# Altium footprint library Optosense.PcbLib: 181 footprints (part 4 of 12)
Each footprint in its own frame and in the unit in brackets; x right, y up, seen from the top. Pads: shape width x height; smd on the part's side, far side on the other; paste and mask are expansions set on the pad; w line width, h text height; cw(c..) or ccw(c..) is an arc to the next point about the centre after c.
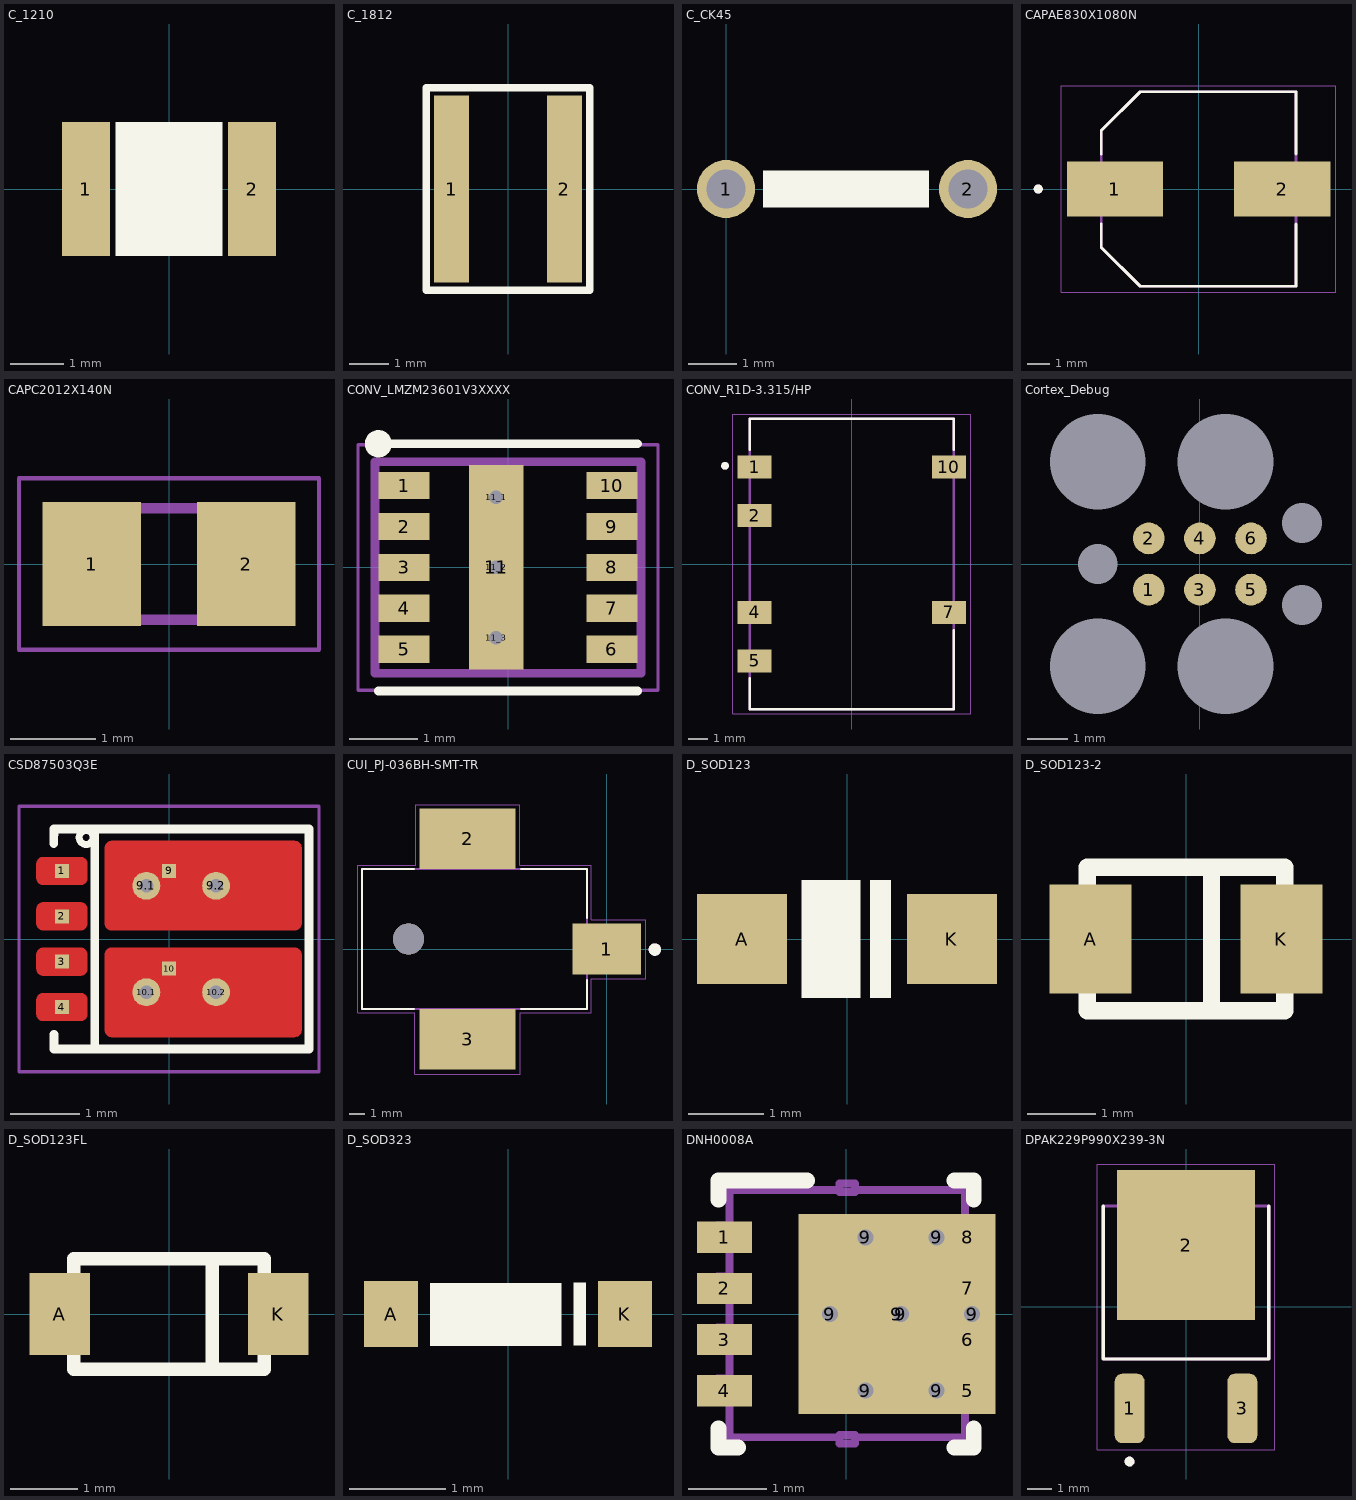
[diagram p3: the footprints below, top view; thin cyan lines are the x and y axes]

## C_1210 [mm]
pads (2):
  rect 0.9x2.5 smd: 1(-1.55,0) 2(1.55,0)
Top Overlay:
  rectangle: -1,-1.25 1,1.25
3D body "12105C335JAT2A.stp": height 2.79, standoff 0, extent -1.65,-1.25 1.65,1.25

## C_1812 [mm]
height 0.55
pads (2):
  rect 0.9x4.8 smd: 1(-1.45,0) 2(1.45,0)
Top Overlay:
  lines w0.2: -2.1,-2.6 -2.1,2.6 2.1,2.6 2.1,-2.6 -2.1,-2.6

## C_CK45 [mm]
pads (2):
  round 1.2 hole 0.8: 1(0,0) 2(5,0)
Top Overlay:
  rectangle: 0.762,-0.381 4.191,0.381
3D body "User Library-TDK_CAP_CK45_.STEP": height 12.5, standoff -5, extent -3.053,-2.503 7.939,2.497

## CAPAE830X1080N [mm]
pads (2):
  rect 4.21x2.42 smd: 1(-3.65,0) 2(3.65,0)
Top Overlay:
  circle w0.2: c-7,0 r0.1
  lines w0.127: -4.25,-1.53 -4.25,-2.55 -2.55,-4.25 4.25,-4.25 4.25,-1.53 ; -4.25,1.53 -4.25,2.55 -2.55,4.25 4.25,4.25 4.25,1.53
Mechanical 13:
  circle w0.2: c-7,0 r0.1
  lines w0.127: -4.25,-2.55 -4.25,2.55 -2.55,4.25 4.25,4.25 4.25,-4.25 -2.55,-4.25 -4.25,-2.55
Mechanical 15:
  lines w0.05: -6.005,-4.5 -6.005,4.5 6.005,4.5 6.005,-4.5 -6.005,-4.5
3D body "EEE-2AA100P.STEP": height 10.5, standoff 0, extent -5,-4.15 5,4.15

## CAPC2012X140N [mm]
pads (2):
  rect 1.15x1.45 smd: 1(-0.9,0) 2(0.9,0)
Mechanical 13:
  region: -0.5,-0.665 -1.023,-0.665 -1.023,0.65 -0.5,0.65
  region: 1,-0.668 0.514,-0.668 0.514,0.65 1,0.65
  lines w0.127: -1,-0.65 1,-0.65 1,0.65 -1,0.65 -1,-0.65
Mechanical 15:
  lines w0.05: -1.75,-1 1.75,-1 1.75,1 -1.75,1 -1.75,-1

## CONV_LMZM23601V3XXXX [mm]
pads (14):
  rect 0.75x0.4 smd paste-0.1 mask+0: 1(-1.525,1.2) 2(-1.525,0.6) 3(-1.525,0) 4(-1.525,-0.6) 5(-1.525,-1.2) 6(1.525,-1.2) 7(1.525,-0.6) 8(1.525,0) 9(1.525,0.6) 10(1.525,1.2)
  rect 0.8x3 smd paste-0.25 mask+0: 11(-0.175,0)
  round 0.4 hole 0.2 mask+0: 11_1(-0.175,1.03) 11_2(-0.175,0) 11_3(-0.175,-1.03)
Top Overlay:
  circle w0.2: c-1.9,1.813 r0.1
  lines w0.127: -1.9,-1.813 1.9,-1.813 ; -1.9,1.813 1.9,1.813
Top Paste:
  region: 1.85,-1.35 1.2,-1.35 1.2,-1.05 1.85,-1.05
  region: 1.85,-0.75 1.2,-0.75 1.2,-0.45 1.85,-0.45
  region: 1.85,-0.15 1.2,-0.15 1.2,0.15 1.85,0.15
  region: 1.85,0.45 1.2,0.45 1.2,0.75 1.85,0.75
  region: 1.85,1.05 1.2,1.05 1.2,1.35 1.85,1.35
  region: -1.2,-1.35 -1.85,-1.35 -1.85,-1.05 -1.2,-1.05
  region: -1.2,-0.75 -1.85,-0.75 -1.85,-0.45 -1.2,-0.45
  region: -1.2,-0.15 -1.85,-0.15 -1.85,0.15 -1.2,0.15
  region: -1.2,0.45 -1.85,0.45 -1.85,0.75 -1.2,0.75
  region: -1.2,1.05 -1.85,1.05 -1.85,1.35 -1.2,1.35
  region: 0.175,-1.446 -0.525,-1.446 -0.525,-0.613 0.175,-0.613
  region: 0.175,-0.416 -0.525,-0.416 -0.525,0.416 0.175,0.416
  region: 0.175,0.613 -0.525,0.613 -0.525,1.446 0.175,1.446
Top Solder:
  region: 1.85,-1.35 1.2,-1.35 1.2,-1.05 1.85,-1.05
  region: 1.85,-0.75 1.2,-0.75 1.2,-0.45 1.85,-0.45
  region: 1.85,1.05 1.2,1.05 1.2,1.35 1.85,1.35
  region: 1.85,0.45 1.2,0.45 1.2,0.75 1.85,0.75
  region: -1.2,-1.35 -1.85,-1.35 -1.85,-1.05 -1.2,-1.05
  region: -1.2,-0.75 -1.85,-0.75 -1.85,-0.45 -1.2,-0.45
  region: -1.2,1.05 -1.85,1.05 -1.85,1.35 -1.2,1.35
  region: -1.2,0.45 -1.85,0.45 -1.85,0.75 -1.2,0.75
  region: 1.85,-0.15 1.2,-0.15 1.2,0.15 1.85,0.15
  region: -1.2,-0.15 -1.85,-0.15 -1.85,0.15 -1.2,0.15
  region: 0.175,-1.45 -0.525,-1.45 -0.525,1.45 0.175,1.45
Mechanical 13:
  lines w0.127: -1.95,-1.55 1.95,-1.55 1.95,1.55 -1.95,1.55 -1.95,-1.55
Mechanical 15:
  lines w0.05: -2.2,-1.8 2.2,-1.8 2.2,1.8 -2.2,1.8 -2.2,-1.8
3D body "PLMZM23601SILR--3DModel-STEP-56544.STEP": height 1.58, standoff 0, extent -1.9,-1.5 1.9,1.5

## CONV_R1D-3.315/HP [mm]
pads (6):
  rect 1.8x1.2 smd: 1(-5.1,5.08) 2(-5.1,2.54) 4(-5.1,-2.54) 5(-5.1,-5.08) 7(5.1,-2.54) 10(5.1,5.08)
Top Overlay:
  circle w0.2: c-6.65,5.15 r0.1
  lines w0.127: -5.35,-6 -5.35,-7.62 5.35,-7.62 5.35,-3.47 ; -5.35,6 -5.35,7.62 5.35,7.62 5.35,6
Mechanical 13:
  circle w0.2: c-6.65,5.15 r0.1
  lines w0.127: -5.35,-7.62 -5.35,7.62 5.35,7.62 5.35,-7.62 -5.35,-7.62
Mechanical 15:
  lines w0.05: -6.25,-7.87 -6.25,7.87 6.25,7.87 6.25,-7.87 -6.25,-7.87
3D body "R1D-3.315-HP--3DModel-STEP-1.STEP": height 7.05, standoff 0.05, extent -5.423,-7.625 5.677,7.625

## Cortex_Debug [mm]
pads (13):
  round 0.787 smd paste+0 mask+0: 1(-1.27,-0.635) 2(-1.27,0.635) 3(0,-0.635) 4(0,0.635) 5(1.27,-0.635) 6(1.27,0.635)
  round 0.787 hole 2.375 paste+0 mask+0: ""(-2.54,-2.54) ""(-2.54,2.54) ""(0.635,-2.54) ""(0.635,2.54)
  round 0.787 hole 0.991 paste+0 mask+0: ""(-2.54,0) ""(2.54,-1.016) ""(2.54,1.016)

## CSD87503Q3E [mm]
pads (10):
  rect 0.2x0.2 smd paste-1 mask+0: 1(-1.535,0.975) 2(-1.535,0.325) 3(-1.535,-0.325) 4(-1.535,-0.975) 9(0,0.975) 10(0,-0.425)
  round 0.4 hole 0.2 mask+0: 9.1(-0.325,0.763) 9.2(0.675,0.763) 10.1(-0.325,-0.763) 10.2(0.675,-0.763)
Top Layer:
  region: 1.805,-0.125 1.81,-0.126 1.816,-0.126 1.821,-0.127 1.826,-0.128 1.831,-0.13 1.836,-0.132 1.841,-0.134 1.845,-0.136 1.85,-0.138 1.854,-0.141 1.859,-0.144 1.863,-0.147 1.867,-0.151 1.871,-0.154 1.874,-0.158 1.878,-0.162 1.881,-0.166 1.884,-0.171 1.887,-0.175 1.889,-0.18 1.891,-0.184 1.893,-0.189 1.895,-0.194 1.897,-0.199 1.898,-0.204 1.899,-0.209 1.899,-0.215 1.9,-0.22 1.9,-0.225 1.9,-1.305 1.9,-1.31 1.899,-1.315 1.899,-1.321 1.898,-1.326 1.897,-1.331 1.895,-1.336 1.893,-1.341 1.891,-1.346 1.889,-1.35 1.887,-1.355 1.884,-1.359 1.881,-1.364 1.878,-1.368 1.874,-1.372 1.871,-1.376 1.867,-1.379 1.863,-1.383 1.859,-1.386 1.854,-1.389 1.85,-1.392 1.845,-1.394 1.841,-1.396 1.836,-1.398 1.831,-1.4 1.826,-1.402 1.821,-1.403 1.816,-1.404 1.81,-1.404 1.805,-1.405 1.8,-1.405 -0.82,-1.405 -0.825,-1.405 -0.83,-1.404 -0.836,-1.404 -0.841,-1.403 -0.846,-1.402 -0.851,-1.4 -0.856,-1.398 -0.861,-1.396 -0.865,-1.394 -0.87,-1.392 -0.874,-1.389 -0.879,-1.386 -0.883,-1.383 -0.887,-1.379 -0.891,-1.376 -0.894,-1.372 -0.898,-1.368 -0.901,-1.364 -0.904,-1.359 -0.907,-1.355 -0.909,-1.35 -0.911,-1.346 -0.913,-1.341 -0.915,-1.336 -0.917,-1.331 -0.918,-1.326 -0.919,-1.321 -0.919,-1.315 -0.92,-1.31 -0.92,-1.305 -0.92,-0.225 -0.92,-0.22 -0.919,-0.215 -0.919,-0.209 -0.918,-0.204 -0.917,-0.199 -0.915,-0.194 -0.913,-0.189 -0.911,-0.184 -0.909,-0.18 -0.907,-0.175 -0.904,-0.171 -0.901,-0.166 -0.898,-0.162 -0.894,-0.158 -0.891,-0.154 -0.887,-0.151 -0.883,-0.147 -0.879,-0.144 -0.874,-0.141 -0.87,-0.138 -0.865,-0.136 -0.861,-0.134 -0.856,-0.132 -0.851,-0.13 -0.846,-0.128 -0.841,-0.127 -0.836,-0.126 -0.83,-0.126 -0.825,-0.125 -0.82,-0.125 1.8,-0.125
  region: 1.805,1.405 1.81,1.404 1.816,1.404 1.821,1.403 1.826,1.402 1.831,1.4 1.836,1.398 1.841,1.396 1.845,1.394 1.85,1.392 1.854,1.389 1.859,1.386 1.863,1.383 1.867,1.379 1.871,1.376 1.874,1.372 1.878,1.368 1.881,1.364 1.884,1.359 1.887,1.355 1.889,1.35 1.891,1.346 1.893,1.341 1.895,1.336 1.897,1.331 1.898,1.326 1.899,1.321 1.899,1.315 1.9,1.31 1.9,1.305 1.9,0.225 1.9,0.22 1.899,0.215 1.899,0.209 1.898,0.204 1.897,0.199 1.895,0.194 1.893,0.189 1.891,0.184 1.889,0.18 1.887,0.175 1.884,0.171 1.881,0.166 1.878,0.162 1.874,0.158 1.871,0.154 1.867,0.151 1.863,0.147 1.859,0.144 1.854,0.141 1.85,0.138 1.845,0.136 1.841,0.134 1.836,0.132 1.831,0.13 1.826,0.128 1.821,0.127 1.816,0.126 1.81,0.126 1.805,0.125 1.8,0.125 -0.82,0.125 -0.825,0.125 -0.83,0.126 -0.836,0.126 -0.841,0.127 -0.846,0.128 -0.851,0.13 -0.856,0.132 -0.861,0.134 -0.865,0.136 -0.87,0.138 -0.874,0.141 -0.879,0.144 -0.883,0.147 -0.887,0.151 -0.891,0.154 -0.894,0.158 -0.898,0.162 -0.901,0.166 -0.904,0.171 -0.907,0.175 -0.909,0.18 -0.911,0.184 -0.913,0.189 -0.915,0.194 -0.917,0.199 -0.918,0.204 -0.919,0.209 -0.919,0.215 -0.92,0.22 -0.92,0.225 -0.92,1.305 -0.92,1.31 -0.919,1.315 -0.919,1.321 -0.918,1.326 -0.917,1.331 -0.915,1.336 -0.913,1.341 -0.911,1.346 -0.909,1.35 -0.907,1.355 -0.904,1.359 -0.901,1.364 -0.898,1.368 -0.894,1.372 -0.891,1.376 -0.887,1.379 -0.883,1.383 -0.879,1.386 -0.874,1.389 -0.87,1.392 -0.865,1.394 -0.861,1.396 -0.856,1.398 -0.851,1.4 -0.846,1.402 -0.841,1.403 -0.836,1.404 -0.83,1.404 -0.825,1.405 -0.82,1.405 1.8,1.405
  region: -1.265,-0.775 -1.26,-0.776 -1.254,-0.776 -1.249,-0.777 -1.244,-0.778 -1.239,-0.78 -1.234,-0.782 -1.229,-0.784 -1.225,-0.786 -1.22,-0.788 -1.216,-0.791 -1.211,-0.794 -1.207,-0.797 -1.203,-0.801 -1.199,-0.804 -1.196,-0.808 -1.192,-0.812 -1.189,-0.816 -1.186,-0.821 -1.183,-0.825 -1.181,-0.83 -1.179,-0.834 -1.177,-0.839 -1.175,-0.844 -1.173,-0.849 -1.172,-0.854 -1.171,-0.859 -1.171,-0.865 -1.17,-0.87 -1.17,-0.875 -1.17,-1.075 -1.17,-1.08 -1.171,-1.085 -1.171,-1.091 -1.172,-1.096 -1.173,-1.101 -1.175,-1.106 -1.177,-1.111 -1.179,-1.116 -1.181,-1.12 -1.183,-1.125 -1.186,-1.129 -1.189,-1.134 -1.192,-1.138 -1.196,-1.142 -1.199,-1.146 -1.203,-1.149 -1.207,-1.153 -1.211,-1.156 -1.216,-1.159 -1.22,-1.162 -1.225,-1.164 -1.229,-1.166 -1.234,-1.168 -1.239,-1.17 -1.244,-1.172 -1.249,-1.173 -1.254,-1.174 -1.26,-1.174 -1.265,-1.175 -1.27,-1.175 -1.8,-1.175 -1.805,-1.175 -1.81,-1.174 -1.816,-1.174 -1.821,-1.173 -1.826,-1.172 -1.831,-1.17 -1.836,-1.168 -1.841,-1.166 -1.845,-1.164 -1.85,-1.162 -1.854,-1.159 -1.859,-1.156 -1.863,-1.153 -1.867,-1.149 -1.871,-1.146 -1.874,-1.142 -1.878,-1.138 -1.881,-1.134 -1.884,-1.129 -1.887,-1.125 -1.889,-1.12 -1.891,-1.116 -1.893,-1.111 -1.895,-1.106 -1.897,-1.101 -1.898,-1.096 -1.899,-1.091 -1.899,-1.085 -1.9,-1.08 -1.9,-1.075 -1.9,-0.875 -1.9,-0.87 -1.899,-0.865 -1.899,-0.859 -1.898,-0.854 -1.897,-0.849 -1.895,-0.844 -1.893,-0.839 -1.891,-0.834 -1.889,-0.83 -1.887,-0.825 -1.884,-0.821 -1.881,-0.816 -1.878,-0.812 -1.874,-0.808 -1.871,-0.804 -1.867,-0.801 -1.863,-0.797 -1.859,-0.794 -1.854,-0.791 -1.85,-0.788 -1.845,-0.786 -1.841,-0.784 -1.836,-0.782 -1.831,-0.78 -1.826,-0.778 -1.821,-0.777 -1.816,-0.776 -1.81,-0.776 -1.805,-0.775 -1.8,-0.775 -1.27,-0.775
  region: -1.265,1.175 -1.26,1.174 -1.254,1.174 -1.249,1.173 -1.244,1.172 -1.239,1.17 -1.234,1.168 -1.229,1.166 -1.225,1.164 -1.22,1.162 -1.216,1.159 -1.211,1.156 -1.207,1.153 -1.203,1.149 -1.199,1.146 -1.196,1.142 -1.192,1.138 -1.189,1.134 -1.186,1.129 -1.183,1.125 -1.181,1.12 -1.179,1.116 -1.177,1.111 -1.175,1.106 -1.173,1.101 -1.172,1.096 -1.171,1.091 -1.171,1.085 -1.17,1.08 -1.17,1.075 -1.17,0.875 -1.17,0.87 -1.171,0.865 -1.171,0.859 -1.172,0.854 -1.173,0.849 -1.175,0.844 -1.177,0.839 -1.179,0.834 -1.181,0.83 -1.183,0.825 -1.186,0.821 -1.189,0.816 -1.192,0.812 -1.196,0.808 -1.199,0.804 -1.203,0.801 -1.207,0.797 -1.211,0.794 -1.216,0.791 -1.22,0.788 -1.225,0.786 -1.229,0.784 -1.234,0.782 -1.239,0.78 -1.244,0.778 -1.249,0.777 -1.254,0.776 -1.26,0.776 -1.265,0.775 -1.27,0.775 -1.8,0.775 -1.805,0.775 -1.81,0.776 -1.816,0.776 -1.821,0.777 -1.826,0.778 -1.831,0.78 -1.836,0.782 -1.841,0.784 -1.845,0.786 -1.85,0.788 -1.854,0.791 -1.859,0.794 -1.863,0.797 -1.867,0.801 -1.871,0.804 -1.874,0.808 -1.878,0.812 -1.881,0.816 -1.884,0.821 -1.887,0.825 -1.889,0.83 -1.891,0.834 -1.893,0.839 -1.895,0.844 -1.897,0.849 -1.898,0.854 -1.899,0.859 -1.899,0.865 -1.9,0.87 -1.9,0.875 -1.9,1.075 -1.9,1.08 -1.899,1.085 -1.899,1.091 -1.898,1.096 -1.897,1.101 -1.895,1.106 -1.893,1.111 -1.891,1.116 -1.889,1.12 -1.887,1.125 -1.884,1.129 -1.881,1.134 -1.878,1.138 -1.874,1.142 -1.871,1.146 -1.867,1.149 -1.863,1.153 -1.859,1.156 -1.854,1.159 -1.85,1.162 -1.845,1.164 -1.841,1.166 -1.836,1.168 -1.831,1.17 -1.826,1.172 -1.821,1.173 -1.816,1.174 -1.81,1.174 -1.805,1.175 -1.8,1.175 -1.27,1.175
  region: -1.265,0.525 -1.26,0.524 -1.254,0.524 -1.249,0.523 -1.244,0.522 -1.239,0.52 -1.234,0.518 -1.229,0.516 -1.225,0.514 -1.22,0.512 -1.216,0.509 -1.211,0.506 -1.207,0.503 -1.203,0.499 -1.199,0.496 -1.196,0.492 -1.192,0.488 -1.189,0.484 -1.186,0.479 -1.183,0.475 -1.181,0.47 -1.179,0.466 -1.177,0.461 -1.175,0.456 -1.173,0.451 -1.172,0.446 -1.171,0.441 -1.171,0.435 -1.17,0.43 -1.17,0.425 -1.17,0.225 -1.17,0.22 -1.171,0.215 -1.171,0.209 -1.172,0.204 -1.173,0.199 -1.175,0.194 -1.177,0.189 -1.179,0.184 -1.181,0.18 -1.183,0.175 -1.186,0.171 -1.189,0.166 -1.192,0.162 -1.196,0.158 -1.199,0.154 -1.203,0.151 -1.207,0.147 -1.211,0.144 -1.216,0.141 -1.22,0.138 -1.225,0.136 -1.229,0.134 -1.234,0.132 -1.239,0.13 -1.244,0.128 -1.249,0.127 -1.254,0.126 -1.26,0.126 -1.265,0.125 -1.27,0.125 -1.8,0.125 -1.805,0.125 -1.81,0.126 -1.816,0.126 -1.821,0.127 -1.826,0.128 -1.831,0.13 -1.836,0.132 -1.841,0.134 -1.845,0.136 -1.85,0.138 -1.854,0.141 -1.859,0.144 -1.863,0.147 -1.867,0.151 -1.871,0.154 -1.874,0.158 -1.878,0.162 -1.881,0.166 -1.884,0.171 -1.887,0.175 -1.889,0.18 -1.891,0.184 -1.893,0.189 -1.895,0.194 -1.897,0.199 -1.898,0.204 -1.899,0.209 -1.899,0.215 -1.9,0.22 -1.9,0.225 -1.9,0.425 -1.9,0.43 -1.899,0.435 -1.899,0.441 -1.898,0.446 -1.897,0.451 -1.895,0.456 -1.893,0.461 -1.891,0.466 -1.889,0.47 -1.887,0.475 -1.884,0.479 -1.881,0.484 -1.878,0.488 -1.874,0.492 -1.871,0.496 -1.867,0.499 -1.863,0.503 -1.859,0.506 -1.854,0.509 -1.85,0.512 -1.845,0.514 -1.841,0.516 -1.836,0.518 -1.831,0.52 -1.826,0.522 -1.821,0.523 -1.816,0.524 -1.81,0.524 -1.805,0.525 -1.8,0.525 -1.27,0.525
  region: -1.265,-0.125 -1.26,-0.126 -1.254,-0.126 -1.249,-0.127 -1.244,-0.128 -1.239,-0.13 -1.234,-0.132 -1.229,-0.134 -1.225,-0.136 -1.22,-0.138 -1.216,-0.141 -1.211,-0.144 -1.207,-0.147 -1.203,-0.151 -1.199,-0.154 -1.196,-0.158 -1.192,-0.162 -1.189,-0.166 -1.186,-0.171 -1.183,-0.175 -1.181,-0.18 -1.179,-0.184 -1.177,-0.189 -1.175,-0.194 -1.173,-0.199 -1.172,-0.204 -1.171,-0.209 -1.171,-0.215 -1.17,-0.22 -1.17,-0.225 -1.17,-0.425 -1.17,-0.43 -1.171,-0.435 -1.171,-0.441 -1.172,-0.446 -1.173,-0.451 -1.175,-0.456 -1.177,-0.461 -1.179,-0.466 -1.181,-0.47 -1.183,-0.475 -1.186,-0.479 -1.189,-0.484 -1.192,-0.488 -1.196,-0.492 -1.199,-0.496 -1.203,-0.499 -1.207,-0.503 -1.211,-0.506 -1.216,-0.509 -1.22,-0.512 -1.225,-0.514 -1.229,-0.516 -1.234,-0.518 -1.239,-0.52 -1.244,-0.522 -1.249,-0.523 -1.254,-0.524 -1.26,-0.524 -1.265,-0.525 -1.27,-0.525 -1.8,-0.525 -1.805,-0.525 -1.81,-0.524 -1.816,-0.524 -1.821,-0.523 -1.826,-0.522 -1.831,-0.52 -1.836,-0.518 -1.841,-0.516 -1.845,-0.514 -1.85,-0.512 -1.854,-0.509 -1.859,-0.506 -1.863,-0.503 -1.867,-0.499 -1.871,-0.496 -1.874,-0.492 -1.878,-0.488 -1.881,-0.484 -1.884,-0.479 -1.887,-0.475 -1.889,-0.47 -1.891,-0.466 -1.893,-0.461 -1.895,-0.456 -1.897,-0.451 -1.898,-0.446 -1.899,-0.441 -1.899,-0.435 -1.9,-0.43 -1.9,-0.425 -1.9,-0.225 -1.9,-0.22 -1.899,-0.215 -1.899,-0.209 -1.898,-0.204 -1.897,-0.199 -1.895,-0.194 -1.893,-0.189 -1.891,-0.184 -1.889,-0.18 -1.887,-0.175 -1.884,-0.171 -1.881,-0.166 -1.878,-0.162 -1.874,-0.158 -1.871,-0.154 -1.867,-0.151 -1.863,-0.147 -1.859,-0.144 -1.854,-0.141 -1.85,-0.138 -1.845,-0.136 -1.841,-0.134 -1.836,-0.132 -1.831,-0.13 -1.826,-0.128 -1.821,-0.127 -1.816,-0.126 -1.81,-0.126 -1.805,-0.125 -1.8,-0.125 -1.27,-0.125
Top Overlay:
  circle w0.1: c-1.188,1.455 r0.1
  rectangle: -1.125,-1.575 -1,1.611
  lines w0.127: -1.652,1.371 -1.651,1.575 2.007,1.575 2.007,-1.575 -1.649,-1.575 -1.648,-1.371
Top Paste:
  drawing of 10 lines, arcs and shapes, not listed
Top Solder:
  drawing of 6 lines, arcs and shapes, not listed
Mechanical 15:
  lines w0.05: -2.15,-1.9 -2.15,1.9 2.15,1.9 2.15,-1.9 -2.15,-1.9
3D body "CSD17551Q3A.STEP": height 0.9, standoff 0, extent -1.599,-1.75 1.701,1.7

## CUI_PJ-036BH-SMT-TR [mm]
pads (4):
  rect 4.4x3.3 smd: 1(0,0)
  rect 6.2x3.9 smd: 2(-8.95,7.1) 3(-8.95,-5.8)
  round 2 hole 2 unplated: ""(-12.75,0.65)
Top Overlay:
  circle w0.4: c3.104,-0.03 r0.2
  lines w0.127: -12.4,-3.85 -15.75,-3.85 -15.75,5.15 -12.4,5.15 ; -5.5,-3.85 -1.25,-3.85 -1.25,-2 ; -5.5,5.15 -1.25,5.15 -1.25,2
Mechanical 13:
  circle w0.4: c3.104,-0.03 r0.2
  lines w0.127: -15.75,-3.85 -15.75,5.15 -1.25,5.15 -1.25,-3.85 -15.75,-3.85
Mechanical 15:
  lines w0.05: -16,-4.1 -16,5.4 -12.3,5.4 -12.3,9.3 -5.6,9.3 -5.6,5.4 -1,5.4 -1,1.9 2.5,1.9 2.5,-1.9 -1,-1.9 -1,-4.1 -5.55,-4.1 -5.55,-8.05 -12.35,-8.05 -12.35,-4.1 -16,-4.1
3D body "CUI_DEVICES_PJ-036BH-SMT-TR.step": height 11, standoff -1.6, extent -15.85,-7.1 1.25,8.1

## D_SOD123 [mm]
pads (2):
  rect 1.2x1.2 smd paste-0.05 mask+0.2: A(-1.4,0) K(1.4,0)
Top Overlay:
  rectangle: 0.305,-0.787 0.584,0.787
  rectangle: -0.61,-0.787 0.178,0.787
3D body "CircuitWorks-SOD123.STEP": height 1.27, standoff 0, extent -1.875,-0.8 1.825,0.8

## D_SOD123-2 [mm]
pads (2):
  rect 1.2x1.6 smd: A(-1.4,0) K(1.4,0)
Top Overlay:
  lines w0.254: 0.375,-1.05 0.375,1.05 ; -1.45,-1.05 1.45,-1.05 1.45,0.8 1.45,1.05 -1.45,1.05 -1.45,0.8 -1.45,-1.05

## D_SOD123FL [mm]
pads (2):
  rect 0.91x1.22 smd: A(-1.635,0) K(1.635,0)
Top Overlay:
  lines w0.2: 0.65,-0.825 0.65,0.825 ; -1.425,-0.825 -1.425,0.825 1.425,0.825 1.425,-0.825 -1.425,-0.825

## D_SOD323 [mm]
pads (2):
  rect 0.56x0.69 smd: A(-1.22,0) K(1.22,0)
Top Overlay:
  rectangle: 0.686,-0.33 0.813,0.33
  rectangle: -0.813,-0.334 0.556,0.326
3D body "User Library-SOD-323.STEP": height 1.1, standoff 0, extent -1.3,-0.7 1.3,0.65

## DNH0008A [mm]
pads (16):
  rect 0.7x0.4 smd paste-0.05 mask-0.051: 1(-1.55,0.975) 2(-1.55,0.325) 3(-1.55,-0.325) 4(-1.55,-0.975) 5(1.55,-0.975) 6(1.55,-0.325) 7(1.55,0.325) 8(1.55,0.975)
  round 0.5 hole 0.203 mask+0: 9(-0.208,0) 9(0.245,-0.975) 9(0.245,0.975) 9(0.697,0) 9(1.15,-0.975) 9(1.15,0.975) 9(1.602,0)
  rect 2.51x2.55 smd paste-1.262 mask-1.257: 9(0.645,0)
Top Overlay:
  lines w0.2: -1.625,-1.453 -1.625,-1.7 -1.378,-1.7 ; -1.625,1.453 -1.625,1.7 -0.5,1.7 ; 1.378,-1.7 1.625,-1.7 1.625,-1.453 ; 1.378,1.7 1.625,1.7 1.625,1.453
Top Paste:
  region: 0.346,0.14 0.345,0.149 0.345,1.176 0.346,1.185 0.349,1.195 0.353,1.203 0.359,1.211 0.367,1.217 0.375,1.221 0.385,1.224 0.394,1.225 1.001,1.225 1.01,1.224 1.02,1.221 1.028,1.217 1.036,1.211 1.042,1.203 1.046,1.195 1.049,1.185 1.05,1.176 1.05,0.149 1.049,0.14 1.046,0.13 1.042,0.122 1.036,0.114 1.028,0.108 1.02,0.104 1.01,0.101 1.001,0.1 0.394,0.1 0.385,0.101 0.375,0.104 0.367,0.108 0.359,0.114 0.353,0.122 0.349,0.13
  region: 0.346,-1.185 0.345,-1.176 0.345,-0.149 0.346,-0.14 0.349,-0.13 0.353,-0.122 0.359,-0.114 0.367,-0.108 0.375,-0.104 0.385,-0.101 0.394,-0.1 1.001,-0.1 1.01,-0.101 1.02,-0.104 1.028,-0.108 1.036,-0.114 1.042,-0.122 1.046,-0.13 1.049,-0.14 1.05,-0.149 1.05,-1.176 1.049,-1.185 1.046,-1.195 1.042,-1.203 1.036,-1.211 1.028,-1.217 1.02,-1.221 1.01,-1.224 1.001,-1.225 0.394,-1.225 0.385,-1.224 0.375,-1.221 0.367,-1.217 0.359,-1.211 0.353,-1.203 0.349,-1.195
  region: 0.144,-0.14 0.145,-0.149 0.145,-1.176 0.144,-1.185 0.141,-1.195 0.137,-1.203 0.131,-1.211 0.123,-1.217 0.115,-1.221 0.105,-1.224 0.096,-1.225 -0.511,-1.225 -0.52,-1.224 -0.53,-1.221 -0.538,-1.217 -0.546,-1.211 -0.552,-1.203 -0.556,-1.195 -0.559,-1.185 -0.56,-1.176 -0.56,-0.149 -0.559,-0.14 -0.556,-0.13 -0.552,-0.122 -0.546,-0.114 -0.538,-0.108 -0.53,-0.104 -0.52,-0.101 -0.511,-0.1 0.096,-0.1 0.105,-0.101 0.115,-0.104 0.123,-0.108 0.131,-0.114 0.137,-0.122 0.141,-0.13
  region: 0.144,1.185 0.145,1.176 0.145,0.149 0.144,0.14 0.141,0.13 0.137,0.122 0.131,0.114 0.123,0.108 0.115,0.104 0.105,0.101 0.096,0.1 -0.511,0.1 -0.52,0.101 -0.53,0.104 -0.538,0.108 -0.546,0.114 -0.552,0.122 -0.556,0.13 -0.559,0.14 -0.56,0.149 -0.56,1.176 -0.559,1.185 -0.556,1.195 -0.552,1.203 -0.546,1.211 -0.538,1.217 -0.53,1.221 -0.52,1.224 -0.511,1.225 0.096,1.225 0.105,1.224 0.115,1.221 0.123,1.217 0.131,1.211 0.137,1.203 0.141,1.195
Top Solder:
  region: -0.559,-1.182 -0.56,-1.172 -0.56,1.172 -0.559,1.182 -0.556,1.192 -0.551,1.201 -0.544,1.209 -0.536,1.216 -0.527,1.221 -0.517,1.224 -0.507,1.225 1.162,1.225 1.172,1.224 1.182,1.221 1.191,1.216 1.199,1.209 1.206,1.201 1.211,1.192 1.214,1.182 1.215,1.172 1.215,-1.172 1.214,-1.182 1.211,-1.192 1.206,-1.201 1.199,-1.209 1.191,-1.216 1.182,-1.221 1.172,-1.224 1.162,-1.225 -0.507,-1.225 -0.517,-1.224 -0.527,-1.221 -0.536,-1.216 -0.544,-1.209 -0.551,-1.201 -0.556,-1.192
  region: 0.925,0.475 0.925,0.175 1.425,0.175 1.425,0.475
  region: 0.925,-0.175 0.925,-0.475 1.425,-0.475 1.425,-0.175
  region: 0.925,-0.825 0.925,-1.125 1.425,-1.125 1.425,-0.825
  region: 0.925,1.125 0.925,0.825 1.425,0.825 1.425,1.125
Mechanical 13:
  lines w0.1: -1.487,-1.119 -1.487,-1.569 -0.087,-1.569 ; -1.487,-0.819 -1.487,-0.469 ; -1.487,-0.169 -1.487,0.181 ; -1.487,0.481 -1.487,0.831 ; -1.487,1.131 -1.487,1.581 -0.087,1.581 ; 0.113,-1.569 1.513,-1.569 1.513,-1.119 ; 0.113,1.581 1.513,1.581 1.513,1.131 ; 1.513,-0.819 1.513,-0.469 ; 1.513,-0.169 1.513,0.181 ; 1.513,0.481 1.513,0.831 ; -1.637,-1.119 -1.637,-0.819 -1.461,-0.819 -1.461,-1.119 -1.637,-1.119 ; -1.637,-0.469 -1.637,-0.169 -1.461,-0.169 -1.461,-0.469 -1.637,-0.469 ; -1.637,0.181 -1.461,0.181 -1.461,0.481 -1.637,0.481 -1.637,0.181 ; -1.637,0.831 -1.637,1.131 -1.461,1.131 -1.461,0.831 -1.637,0.831 ; -0.087,-1.649 -0.087,-1.543 0.113,-1.543 0.113,-1.649 -0.087,-1.649 ; -0.087,1.554 0.113,1.554 0.113,1.661 -0.087,1.661 -0.087,1.554 ; 1.486,-1.119 1.486,-0.819 1.663,-0.819 1.663,-1.119 1.486,-1.119 ; 1.486,-0.469 1.486,-0.169 1.663,-0.169 1.663,-0.469 1.486,-0.469 ; 1.486,0.181 1.486,0.481 1.663,0.481 1.663,0.181 1.486,0.181 ; 1.486,0.831 1.486,1.131 1.663,1.131 1.663,0.831 1.486,0.831
3D body "CSD17551Q3A.STEP": height 0.9, standoff 0, extent -1.65,-1.723 1.65,1.727
3D body: height 0.25, standoff 0, extent 0,0 0.254,0.254

## DPAK229P990X239-3N [mm]
pads (3):
  rrect50% 1.22x2.83 smd: 1(-2.29,-4.14) 3(2.29,-4.14)
  rect 5.63x6.1 smd paste-4: 2(0,2.51)
Top Overlay:
  circle w0.2: c-2.3,-6.3 r0.1
  lines w0.127: -3.37,4.098 -3.37,-2.123 3.37,-2.123 3.37,4.098
Top Paste:
  region: 2.535,-0.25 1.225,-0.25 1.225,1.21 2.535,1.21
  region: 0.655,-0.25 -0.655,-0.25 -0.655,1.21 0.655,1.21
  region: -1.225,-0.25 -2.535,-0.25 -2.535,1.21 -1.225,1.21
  region: 2.535,3.81 1.225,3.81 1.225,5.27 2.535,5.27
  region: 0.655,3.81 -0.655,3.81 -0.655,5.27 0.655,5.27
  region: -1.225,3.81 -2.535,3.81 -2.535,5.27 -1.225,5.27
  region: 2.535,1.78 1.225,1.78 1.225,3.24 2.535,3.24
  region: -1.225,1.78 -2.535,1.78 -2.535,3.24 -1.225,3.24
  region: 0.655,1.78 -0.655,1.78 -0.655,3.24 0.655,3.24
Mechanical 13:
  circle w0.2: c-2.3,-6.3 r0.1
  lines w0.127: -3.37,-2.123 3.37,-2.123 3.37,4.098 -3.37,4.098 -3.37,-2.123
Mechanical 15:
  lines w0.05: -3.62,-5.81 3.62,-5.81 3.62,5.81 -3.62,5.81 -3.62,-5.81
3D body "step_temp.STEP": height 2.52, standoff 0, extent -3.27,-4.952 3.27,4.952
